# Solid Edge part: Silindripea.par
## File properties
Author: Türk
Template: iso part.par
Last saved by: Türk
Revision: 58
Application: Solid Edge
Accuracy: 0,990
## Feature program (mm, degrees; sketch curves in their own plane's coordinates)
sketch for "unnamed Hole 1" plane through (0, 99.8478, -73.8819) normal (0, 1, 0) x-axis (1, 0, 0)
hole "unnamed Hole 1" finite
sketch for "unnamed Hole 2" plane through (-360, 60, 0) normal (0, 1, 0) x-axis (-1, 0, 0)
hole "unnamed Hole 2" through
sketch for "unnamed Hole 3" plane through (0, 60, 0) normal (0, 1, 0) x-axis (1, 0, 0)
hole "unnamed Hole 3" through
sketch for "unnamed Hole 4" plane through (0, 99.8478, -73.8819) normal (0, 1, 0) x-axis (1, 0, 0)
hole "unnamed Hole 4" finite
sketch for "unnamed Hole 5" plane through (240, 60, 0) normal (0, 1, 0) x-axis (1, 0, 0)
hole "unnamed Hole 5" through
hole "unnamed Hole 6" finite
hole "unnamed Hole 7" finite
hole "unnamed Hole 8" finite
hole "unnamed Hole 9" finite
hole "unnamed Hole 10" finite
hole "unnamed Hole 11" finite
hole "unnamed Hole 12" finite
pattern "PatternOccurrence_4"  XCount = 6; YCount = 2; XOffset = 120.4 mm; YOffset = 45 mm
pattern "unnamed Pattern 2" of "unnamed Hole 4"
sketch for "unnamed Hole 13" plane through (360, 60, 0) normal (0, 1, 0) x-axis (1, 0, 0)
hole "unnamed Hole 13" through
sketch for "unnamed Hole 14" plane through (0, 60, 0) normal (0, 1, 0) x-axis (-1, 0, 0)
hole "unnamed Hole 14" through
pattern "unnamed Pattern 1" of "unnamed Hole 3", "unnamed Hole 2", "unnamed Hole 14", "unnamed Hole 13", "unnamed Hole 5"
sketch for "unnamed Hole 15" plane through (0, 99.8478, 73.8819) normal (0, 1, 0) x-axis (1, 0, 0)
  hole centre (-301, 0.1319) bore radius 2.7295
hole "unnamed Hole 15" finite
pattern "unnamed Pattern 3" of "unnamed Hole 15", "unnamed Hole 4", "unnamed Hole 1"
pattern "unnamed Pattern 4" of "unnamed Hole 15"
pattern "PatternOccurrence_3"  YCount = 2; XOffset = 120.4 mm; YOffset = 45 mm
hole "unnamed Hole 16" finite
hole "unnamed Hole 17" finite
hole "unnamed Hole 18" finite
hole "unnamed Hole 19" finite
hole "unnamed Hole 20" finite
hole "unnamed Hole 21" finite
hole "unnamed Hole 22" finite
hole "unnamed Hole 23" finite
hole "unnamed Hole 24" finite
hole "unnamed Hole 25" finite
hole "unnamed Hole 26" finite
sketch for "Hole_120" plane through (0, 99.8478, 51.25) normal (0, 1, 0) x-axis (-1, 0, 0)
hole "Hole_120" diameter 6 finite
pattern "unnamed Pattern 5" of "Hole_120"
sketch for "unnamed Hole 27" plane through (0, 99.8478, 51.25) normal (0, 1, 0) x-axis (-1, 0, 0)
  hole centre (-60, -125) bore radius 2.7295
  dimension = 2.7295
hole "unnamed Hole 27" finite
sketch for "unnamed Hole 28" plane through (0, 99.8478, 51.25) normal (0, 1, 0) x-axis (-1, 0, 0)
hole "unnamed Hole 28" finite
sketch for "Hole_121" plane through (0, 99.8478, 51.25) normal (0, 1, 0) x-axis (-1, 0, 0)
hole "Hole_121" diameter 6 finite
pattern "unnamed Pattern 6" of "Hole_121", "unnamed Hole 28", "unnamed Hole 27"
Other named dimensions: "Hole_1": Diameter = 12 mm; CounterBoreDiameter = 25 mm
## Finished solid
Body 1: sheet body, 4 faces, 260 edges, 236 vertices.
  Faces by surface: plane 4
  Edges by curve: line 236, circle 24
Body 2: sheet body, 2 faces, 65 edges, 65 vertices.
  Faces by surface: plane 2
  Edges by curve: line 62, circle 2, intersection 1
Body 3: solid body, 997 faces, 2467 edges, 1454 vertices.
  Faces by surface: plane 523, cylinder 369, blend 80, cone 10, swept 10, torus 5
  Edges by curve: line 1229, circle 853, intersection 245, ellipse 140
Body 4: sheet body, 1 face, 2 edges, 0 vertices.
  Faces by surface: cylinder 1
  Edges by curve: circle 2
Bounding box of the edges (mm; curved faces can reach further): 660.000 x 100.848 x 187.500, from (-330, -1, -92.5) to (330, 99.8478, 95).
Cylindrical faces by radius (mm): R2.7295 x25, R3 x20, R3.5 x56, R5 x20, R5.7295 x5, R5.9952 x20, R7.3756 x24, R8.5 x32, R9 x24, R10 x54, R11 x20, R12 x20, R12.5 x17, R15 x10, R44 x5, R44.5 x5, R47.5 x5, R80 x8
Conical faces (half-angle, radius in mm at the cone's reference point): 85 deg R7.5 x10
Toroidal faces (ring radius, tube radius in mm): R42 r2 x5
Planar faces by outward normal: +x 56, +y 101, +z 36, -x 56, -y 67, -z 31, oblique 176
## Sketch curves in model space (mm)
line (307, 99.8478, -61.25) -> (311, 99.8478, -61.25)
line (307, 99.8478, 61.25) -> (311, 99.8478, 61.25)
arc centre (22.4524, 38.4154, 90) radius 8.5 from (22.6359, 46.9134, 90) through (22.5442, 46.9149, 90) to (22.4524, 46.9154, 90)
arc centre (22.4524, 15.4154, 90) radius 8.5 from (22.6359, 6.9174, 90) through (22.5442, 6.9159, 90) to (22.4524, 6.9154, 90)
arc centre (97.5, 38.4154, 90) radius 8.5 from (97.3165, 46.9134, 90) through (97.4083, 46.9149, 90) to (97.5, 46.9154, 90)
arc centre (97.5, 15.4154, 90) radius 8.5 from (97.3165, 6.9174, 90) through (97.4083, 6.9159, 90) to (97.5, 6.9154, 90)
arc centre (244.5, 38.4154, 90) radius 8.5 from (244.5, 46.9154, 90) through (244.3772, 46.9145, 90) to (244.2545, 46.9119, 90)
arc centre (262.5, 38.4154, 90) radius 8.5 from (262.6835, 46.9134, 90) through (262.5917, 46.9149, 90) to (262.5, 46.9154, 90)
arc centre (244.5, 15.4154, 90) radius 8.5 from (244.5, 6.9154, 90) through (244.3772, 6.9163, 90) to (244.2545, 6.919, 90)
arc centre (262.5, 15.4154, 90) radius 8.5 from (262.6835, 6.9174, 90) through (262.5917, 6.9159, 90) to (262.5, 6.9154, 90)
arc centre (-22.4524, 38.4154, 90) radius 8.5 from (-22.6359, 46.9134, 90) through (-22.5442, 46.9149, 90) to (-22.4524, 46.9154, 90)
arc centre (-22.4524, 15.4154, 90) radius 8.5 from (-22.6359, 6.9174, 90) through (-22.5442, 6.9159, 90) to (-22.4524, 6.9154, 90)
arc centre (-97.5, 38.4154, 90) radius 8.5 from (-97.3165, 46.9134, 90) through (-97.4083, 46.9149, 90) to (-97.5, 46.9154, 90)
arc centre (-97.5, 15.4154, 90) radius 8.5 from (-97.3165, 6.9174, 90) through (-97.4083, 6.9159, 90) to (-97.5, 6.9154, 90)
arc centre (-244.5, 38.4154, 90) radius 8.5 from (-244.5, 46.9154, 90) through (-244.3772, 46.9145, 90) to (-244.2545, 46.9119, 90)
arc centre (-262.5, 38.4154, 90) radius 8.5 from (-262.6835, 46.9134, 90) through (-262.5917, 46.9149, 90) to (-262.5, 46.9154, 90)
arc centre (-244.5, 15.4154, 90) radius 8.5 from (-244.5, 6.9154, 90) through (-244.3772, 6.9163, 90) to (-244.2545, 6.919, 90)
arc centre (-262.5, 15.4154, 90) radius 8.5 from (-262.6835, 6.9174, 90) through (-262.5917, 6.9159, 90) to (-262.5, 6.9154, 90)
line (-183.3295, 99.8478, 90) -> (-180.3295, 99.8478, 90)
line (-0.0357, 6.9193, 90) -> (-4.2069, 6.9197, 90)
line (0.0357, 6.9193, 90) -> (-4.2069, 6.9197, 90)
line (-330, 0, -79.9618) -> (-330, 0, -80)
line (-330, 0, 80) -> (-330, 0, 79.9618)
line (-330, 0, 80) -> (-330, 0, 79.9618)
line (-180, 99.8478, 76.25) -> (-180, 60, 76.25)
line (-170, 99.8478, 76.25) -> (-180, 99.8478, 76.25)
line (-60, 99.8478, 76.25) -> (-60, 60, 76.25)
line (-50, 99.8478, 76.25) -> (-60, 99.8478, 76.25)
line (-330, 63.8026, 28.9938) -> (-330, 80.9094, 28.9938)
line (-240, 99.8478, 76.25) -> (-240, 84.8478, 76.25)
line (-228.5464, 60, 0) -> (-252.0722, 60, 0)
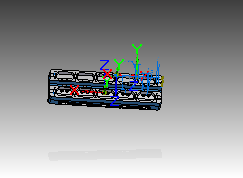
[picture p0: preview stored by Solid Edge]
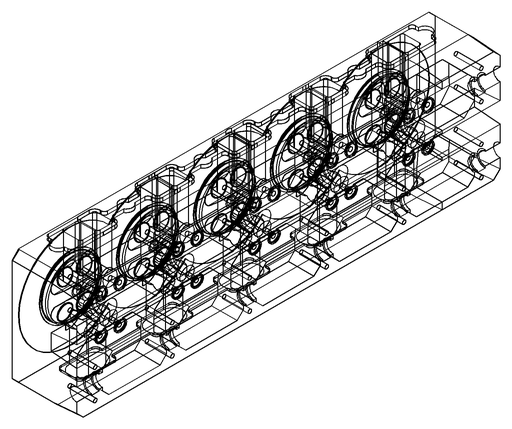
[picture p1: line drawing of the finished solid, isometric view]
